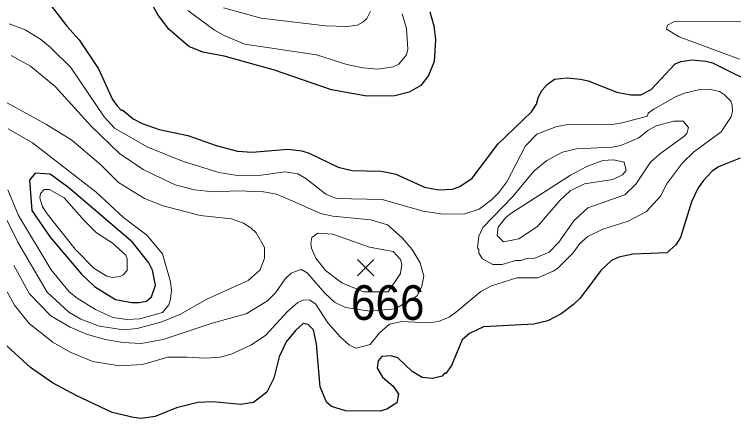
# Model space of a CAD drawing. Extents: x 423 to 448.8, y 7456.3 to 7484.
# Drawn here: x 438.652 to 440.312, y 7467.51 to 7468.444 of the extents above; entities that cross this region are included whole.
import ezdxf
from ezdxf.enums import TextEntityAlignment as Align

# ---------------------------------------------------------------- set-up
doc = ezdxf.new("R2010")
doc.units = 0
doc.header["$LTSCALE"] = 0.032
for name, color, linetype, lineweight in [('1', 7, 'Continuous', 25), ('2', 7, 'Continuous', 13), ('21', 7, 'Continuous', 25)]:
    doc.layers.add(name, color=color, linetype=linetype, lineweight=lineweight)
doc.layers.add('61', color=7, linetype='Continuous')

msp = doc.modelspace()

# ---------------------------------------------------------------- linework, layer by layer
at = {"layer": '1'}
for points in [[(439.6109, 7468.4494), (439.6202, 7468.4169), (439.624, 7468.3844), (439.6209, 7468.3349), (439.6078, 7468.3024), (439.59, 7468.2792), (439.5629, 7468.2638), (439.5304, 7468.2552), (439.4655, 7468.2545), (439.3835, 7468.2692), (439.252, 7468.3148), (439.136, 7468.3473), (439.0865, 7468.3566), (439.0547, 7468.3697), (439.0083, 7468.4091), (438.9836, 7468.4417), (438.8923, 7468.6056)], [(438.7345, 7468.4664), (438.7732, 7468.4161), (438.8011, 7468.3844), (438.8459, 7468.3179), (438.8784, 7468.2467), (438.8885, 7468.2328), (438.8985, 7468.222), (438.9024, 7468.222), (438.9263, 7468.2026), (438.9465, 7468.1918), (438.9859, 7468.1779), (439.0524, 7468.164), (439.1174, 7468.1408), (439.1669, 7468.1276), (439.2009, 7468.1253), (439.2829, 7468.1323), (439.3154, 7468.1284), (439.3324, 7468.123), (439.399, 7468.0905), (439.4314, 7468.0828), (439.498, 7468.0812), (439.515, 7468.0781), (439.532, 7468.0742), (439.5985, 7468.0441), (439.631, 7468.0379), (439.6635, 7468.0394), (439.6797, 7468.0456), (439.7083, 7468.065), (439.7679, 7468.1438), (439.8452, 7468.2181), (439.8568, 7468.2359), (439.8615, 7468.2529), (439.87, 7468.2684), (439.8816, 7468.2815), (439.8986, 7468.2939), (439.928, 7468.297), (439.9589, 7468.2939), (439.976, 7468.2901), (440.0425, 7468.2638), (440.075, 7468.2576), (440.0981, 7468.2575), (440.1214, 7468.2699), (440.177, 7468.3295), (440.1902, 7468.3349), (440.2157, 7468.3388), (440.2482, 7468.3357), (440.2637, 7468.3318), (440.3797, 7468.2738)], [(440.3271, 7468.1114), (440.2776, 7468.0912), (440.2629, 7468.0812), (440.2428, 7468.0595), (440.2304, 7468.0426), (440.2149, 7468.0101), (440.1894, 7467.9281), (440.1786, 7467.9111), (440.1577, 7467.8925), (440.0796, 7467.8894), (440.0471, 7467.8824), (440.0301, 7467.8747), (440.0053, 7467.8522), (439.9582, 7467.7881), (439.9427, 7467.7734), (439.9141, 7467.7517), (439.8831, 7467.7355), (439.8507, 7467.7277), (439.7346, 7467.7216), (439.7021, 7467.7061), (439.6851, 7467.6914), (439.6611, 7467.6326), (439.648, 7467.614), (439.6441, 7467.614), (439.6395, 7467.6078), (439.6171, 7467.6024), (439.5931, 7467.6047), (439.5699, 7467.6187), (439.5366, 7467.6504), (439.5212, 7467.655), (439.5003, 7467.6535), (439.4918, 7467.6434), (439.4894, 7467.6264), (439.5018, 7467.6055), (439.5258, 7467.5847), (439.5382, 7467.5661), (439.535, 7467.546), (439.5119, 7467.5313), (439.4964, 7467.5266), (439.416, 7467.5274), (439.3835, 7467.5374), (439.3719, 7467.5475), (439.3579, 7467.5831), (439.3494, 7467.6821), (439.3425, 7467.7146), (439.337, 7467.72), (439.3301, 7467.7269), (439.3185, 7467.7293), (439.3007, 7467.7131), (439.279, 7467.6868), (439.2628, 7467.6527), (439.2504, 7467.6032), (439.2342, 7467.5707), (439.204, 7467.5468), (439.1747, 7467.5421), (439.1097, 7467.5483), (439.0756, 7467.5468), (439.0261, 7467.5344), (438.9766, 7467.5142), (438.9442, 7467.5096), (438.9271, 7467.5119), (438.8776, 7467.5235), (438.7941, 7467.563), (438.74, 7467.5924), (438.6889, 7467.628), (438.627, 7467.6844)]]:
    msp.add_lwpolyline(points, dxfattribs=at)
msp.add_lwpolyline([(438.6867, 7468.0605), (438.692, 7467.9907), (438.7345, 7467.9288), (438.8065, 7467.843), (438.8366, 7467.8152), (438.8853, 7467.785), (438.9225, 7467.778), (438.9395, 7467.778), (438.9565, 7467.7811), (438.9681, 7467.7912), (438.9774, 7467.8183), (438.9704, 7467.8523), (438.9619, 7467.8693), (438.9248, 7467.9172), (438.7778, 7468.0425), (438.7345, 7468.0742), (438.6997, 7468.0766)], close=True, dxfattribs=at)
at = {"layer": '2'}
for points in [[(439.5467, 7468.4448), (439.5567, 7468.4107), (439.5598, 7468.3628), (439.5567, 7468.3504), (439.5389, 7468.3287), (439.5258, 7468.3225), (439.4918, 7468.3171), (439.4562, 7468.3202), (439.4191, 7468.3279), (439.3495, 7468.3504), (439.1839, 7468.3751), (439.1375, 7468.3937), (439.1135, 7468.4068), (439.0524, 7468.4524)], [(439.4739, 7468.4509), (439.4654, 7468.4339), (439.4562, 7468.4254), (439.4438, 7468.4185), (439.4191, 7468.4154), (439.3696, 7468.4169), (439.2211, 7468.4347), (439.1344, 7468.4587)], [(438.6394, 7468.4215), (438.6765, 7468.4076), (438.7121, 7468.3859), (438.7353, 7468.3674), (438.7817, 7468.321), (438.8591, 7468.2065), (438.883, 7468.181), (438.9596, 7468.1369), (439.0401, 7468.1044), (439.1236, 7468.0781), (439.1716, 7468.0704), (439.2164, 7468.0711), (439.2767, 7468.0796), (439.3061, 7468.075), (439.3247, 7468.0642), (439.3711, 7468.0278), (439.3943, 7468.0185), (439.5011, 7468.0155), (439.5954, 7467.9892), (439.6418, 7467.9822), (439.6913, 7467.983), (439.7246, 7467.9938), (439.7532, 7468.0147), (439.7702, 7468.0317), (439.7887, 7468.0565), (439.8313, 7468.14), (439.8576, 7468.1671), (439.9017, 7468.1841)], [(440.3256, 7468.3403), (440.1863, 7468.3914), (440.1569, 7468.4092), (440.1592, 7468.4185), (440.174, 7468.4262), (440.1863, 7468.4277), (440.3488, 7468.4269)], [(439.2767, 7467.8322), (439.2907, 7467.8453), (439.3108, 7467.853), (439.3162, 7467.853), (439.3286, 7467.8453), (439.3686, 7467.7996), (439.3911, 7467.7785), (439.4162, 7467.7663), (439.4722, 7467.7581), (439.5309, 7467.7635), (439.5814, 7467.7936), (439.5923, 7467.8159), (439.597, 7467.8384), (439.5884, 7467.8693), (439.5699, 7467.9002), (439.5467, 7467.9273), (439.5134, 7467.9575), (439.4748, 7467.969), (439.3866, 7467.9776), (439.3587, 7467.9838), (439.286, 7468.0155), (439.2566, 7468.0278), (439.2272, 7468.0333), (439.1685, 7468.0356), (439.1112, 7468.0332), (439.0679, 7468.0379), (439.0231, 7468.0495), (438.9921, 7468.0642), (438.9488, 7468.0851), (438.8946, 7468.1222), (438.8289, 7468.1856), (438.7462, 7468.2769), (438.6889, 7468.3241), (438.6441, 7468.3488)], [(439.9017, 7468.1841), (439.9249, 7468.188), (440.0316, 7468.1895), (440.0548, 7468.1926), (440.1136, 7468.2081), (440.1151, 7468.215), (440.1283, 7468.2243), (440.1778, 7468.2529), (440.1987, 7468.2614), (440.2343, 7468.2699), (440.2559, 7468.2707), (440.2792, 7468.2653), (440.2907, 7468.2575), (440.3054, 7468.2429), (440.3085, 7468.2336), (440.3093, 7468.2189), (440.3062, 7468.2065), (440.283, 7468.1725), (440.2196, 7468.1253), (440.194, 7468.1005), (440.1569, 7468.051), (440.1438, 7468.024), (440.1113, 7467.9884), (440.0688, 7467.966), (440.01, 7467.9474), (439.9759, 7467.9304), (439.9573, 7467.9142), (439.9419, 7467.8925), (439.9055, 7467.8561), (439.8955, 7467.8499), (439.8599, 7467.8352), (439.812, 7467.8345), (439.7532, 7467.8167), (439.7284, 7467.8035), (439.6728, 7467.7571), (439.6557, 7467.744), (439.631, 7467.7339), (439.6078, 7467.7308), (439.5463, 7467.734), (439.5178, 7467.728), (439.4945, 7467.7077), (439.4732, 7467.6805), (439.4407, 7467.672), (439.4253, 7467.679), (439.4043, 7467.6976), (439.3757, 7467.7308), (439.3471, 7467.7749), (439.3339, 7467.7834), (439.3201, 7467.7842), (439.3061, 7467.778), (439.2829, 7467.7579), (439.2311, 7467.7014), (439.1978, 7467.679), (439.1522, 7467.6589), (439.1267, 7467.6519), (439.0927, 7467.6489), (439.0493, 7467.6519), (439.006, 7467.6519), (438.9472, 7467.6349), (438.8947, 7467.6318), (438.8328, 7467.6419), (438.7809, 7467.6628), (438.7407, 7467.686), (438.6858, 7467.7293), (438.6518, 7467.7718), (438.6348, 7467.8027)], [(438.6092, 7468.0178), (438.6595, 7467.9173), (438.7275, 7467.802), (438.7771, 7467.7556), (438.8049, 7467.7393), (438.8482, 7467.7231), (438.9039, 7467.7146), (438.9349, 7467.7177), (438.9921, 7467.7332), (439.0339, 7467.7501), (439.0958, 7467.7858), (439.1917, 7467.829), (439.2195, 7467.853), (439.2295, 7467.8801), (439.2288, 7467.9048), (439.2102, 7467.9389), (439.1978, 7467.9505), (439.1808, 7467.9613), (439.153, 7467.9714), (439.0803, 7467.9791), (438.9952, 7468.0015), (438.9519, 7468.0178), (438.8923, 7468.0549), (438.8513, 7468.0959), (438.784, 7468.1531), (438.726, 7468.1895), (438.6348, 7468.239)], [(438.6371, 7468.1794), (438.6936, 7468.147), (438.8405, 7468.0325), (438.9039, 7467.9744), (438.9573, 7467.9335), (438.9937, 7467.8902), (439.0122, 7467.826), (439.0145, 7467.8059), (439.0122, 7467.7858), (439.0083, 7467.7726), (438.9937, 7467.7548), (438.9411, 7467.7401), (438.9117, 7467.7386), (438.8792, 7467.7432), (438.839, 7467.7618), (438.7964, 7467.7881), (438.7786, 7467.8027), (438.7368, 7467.853), (438.661, 7467.9791), (438.6363, 7468.0379)], [(438.6502, 7467.8631), (438.6866, 7467.7981), (438.7361, 7467.747), (438.7809, 7467.7208), (438.8204, 7467.7038), (438.8622, 7467.6921), (438.9024, 7467.6852), (438.9442, 7467.6829), (438.9952, 7467.6921), (439.1081, 7467.7301), (439.187, 7467.7517), (439.2357, 7467.7819), (439.2543, 7467.8004), (439.2767, 7467.8322)]]:
    msp.add_lwpolyline(points, dxfattribs=at)
for points in [[(439.821, 7467.8749), (439.8349, 7467.8793), (439.8529, 7467.8801), (439.8862, 7467.894), (439.9086, 7467.9172), (439.9434, 7467.9668), (439.9759, 7467.9969), (440.061, 7468.0263), (440.0865, 7468.051), (440.1206, 7468.1021), (440.1407, 7468.1207), (440.1971, 7468.1617), (440.2041, 7468.1686), (440.208, 7468.1825), (440.1956, 7468.1972), (440.174, 7468.1972), (440.1337, 7468.1864), (440.1144, 7468.1756), (440.0935, 7468.1585), (440.0518, 7468.1408), (440.0316, 7468.1369), (439.9497, 7468.133), (439.9172, 7468.1253), (439.8808, 7468.1059), (439.8507, 7468.0812), (439.8027, 7468.0224), (439.733, 7467.9513), (439.7238, 7467.9312), (439.7207, 7467.9041), (439.7238, 7467.9002), (439.7238, 7467.8917), (439.7323, 7467.8785), (439.7563, 7467.8654), (439.7779, 7467.8654), (439.8089, 7467.8747)], [(439.8595, 7467.9536), (439.9109, 7468.0139), (439.9349, 7468.0356), (439.9682, 7468.0518), (440.0332, 7468.0619), (440.0556, 7468.0727), (440.0641, 7468.0827), (440.0594, 7468.1021), (440.0347, 7468.1075), (440.01, 7468.106), (439.9729, 7468.0921), (439.9357, 7468.0719), (439.7981, 7467.9837), (439.7864, 7467.9745), (439.7687, 7467.952), (439.7663, 7467.9327), (439.781, 7467.918), (439.8166, 7467.9249)], [(438.813, 7467.9675), (438.7663, 7468.0194), (438.733, 7468.0387), (438.7206, 7468.0387), (438.7121, 7468.0294), (438.7106, 7468.0194), (438.7167, 7467.9992), (438.7275, 7467.983), (438.7918, 7467.901), (438.8358, 7467.8561), (438.8653, 7467.8391), (438.8776, 7467.836), (438.8962, 7467.8376), (438.9023, 7467.8414), (438.9124, 7467.8515), (438.9124, 7467.8786), (438.9093, 7467.8871), (438.8776, 7467.9157), (438.8413, 7467.9389)], [(439.4078, 7467.8237), (439.4577, 7467.8024), (439.5146, 7467.8024), (439.5431, 7467.8451), (439.5459, 7467.8662), (439.5428, 7467.877), (439.5258, 7467.8956), (439.4717, 7467.9056), (439.3866, 7467.9358), (439.3525, 7467.9381), (439.3386, 7467.928), (439.3363, 7467.9142), (439.3378, 7467.9033), (439.3479, 7467.8801), (439.3703, 7467.8515)]]:
    msp.add_lwpolyline(points, close=True, dxfattribs=at)
at = {"layer": '21'}
for p, q in [((439.4441, 7467.8772), (439.4816, 7467.8397)), ((439.4816, 7467.8772), (439.4441, 7467.8397))]:
    msp.add_line(p, q, dxfattribs=at)

# ---------------------------------------------------------------- texts
at = {"layer": '61', "width": 0.95}
msp.add_text('666', height=0.08, dxfattribs=at).set_placement((439.5136, 7467.7377), align=Align.CENTER)

doc.saveas('drawing.dxf')
